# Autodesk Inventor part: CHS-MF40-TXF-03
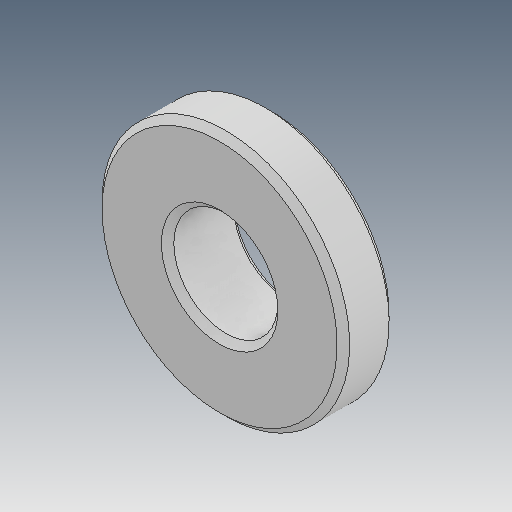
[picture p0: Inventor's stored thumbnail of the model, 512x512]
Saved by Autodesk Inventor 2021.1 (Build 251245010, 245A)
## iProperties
Created: 2019-04
Part Number: CHS-MF40-TXF-03
Material: Ogólny
Document SubType Name: Modeling
Designer: user
Density: 1 g/cm^3
Appearance: Domyślna
Author: user
Revision Number: ÈÎºÎ
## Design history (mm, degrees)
feature "ÊäÈë1"
node "Bryła1"
